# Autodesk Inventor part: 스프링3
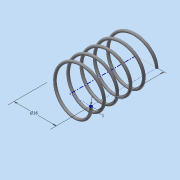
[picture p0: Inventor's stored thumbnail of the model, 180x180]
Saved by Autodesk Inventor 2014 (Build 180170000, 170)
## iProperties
Created: 2015-06
Part Number: 스프링3
Material: 강철, 연강
Document SubType Name: Modeling
Designer: MYHOME
Density: 7.86 g/cm^3
Appearance: 강철
Mass: 1.53535 g
Surface Area: 7.89042 cm^2
Volume: 0.195337 cm^3
Author: MYHOME
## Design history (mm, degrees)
sketch "스케치1"
  geometry: L1 (0, 0)-(8, 0); L2 (8, 0)-(8, 21.5); L3 (8, 21.5)-(0, 21.5); L4 (0, 21.5)-(0, 0); C1 r 0.5 at (8, 0)
  constraints: 8 end point, 2 parallel, 1 centre point, 1 coincident, 1 horizontal, 1 perpendicular
  dimensions: "d0" = 16 diameter of L2 L4; "d1" = 21.5 distance of L1.end L2.end (derived); "d2" = 1 diameter of C1
feature "코일1" sketch "스케치1" pitch "d3" = 10; turns "d5" = 5; dims "d4" = 21.5 (= d1), "d6" = 0, angle "d7" = 90 deg, angle "d8" = 90 deg, "d9" = 0, "d10" = 0
node "작업 평면1"
sketch "스케치2"
  geometry: L1 (-8.5, 0)-(-7.5, 0) reference; 1 further point
  constraints: 1 horizontal alignment
extrude "돌출1" cut sketch "스케치2" stored distance "d12" = 10; taper "d13" = 0 deg
node "작업 평면2"
sketch "스케치3"
  geometry: L1 (8.5, 0)-(7.5, 0) reference; 1 further point
  constraints: 1 horizontal alignment
extrude "돌출2" cut sketch "스케치3" stored distance "d15" = 10; taper "d16" = 0 deg
node "솔리드1"
node "절단 모서리 투영1"
node "절단 모서리 투영2"
other parameters: "d11" = 0, "d14" = -21.5 (= -d1)
